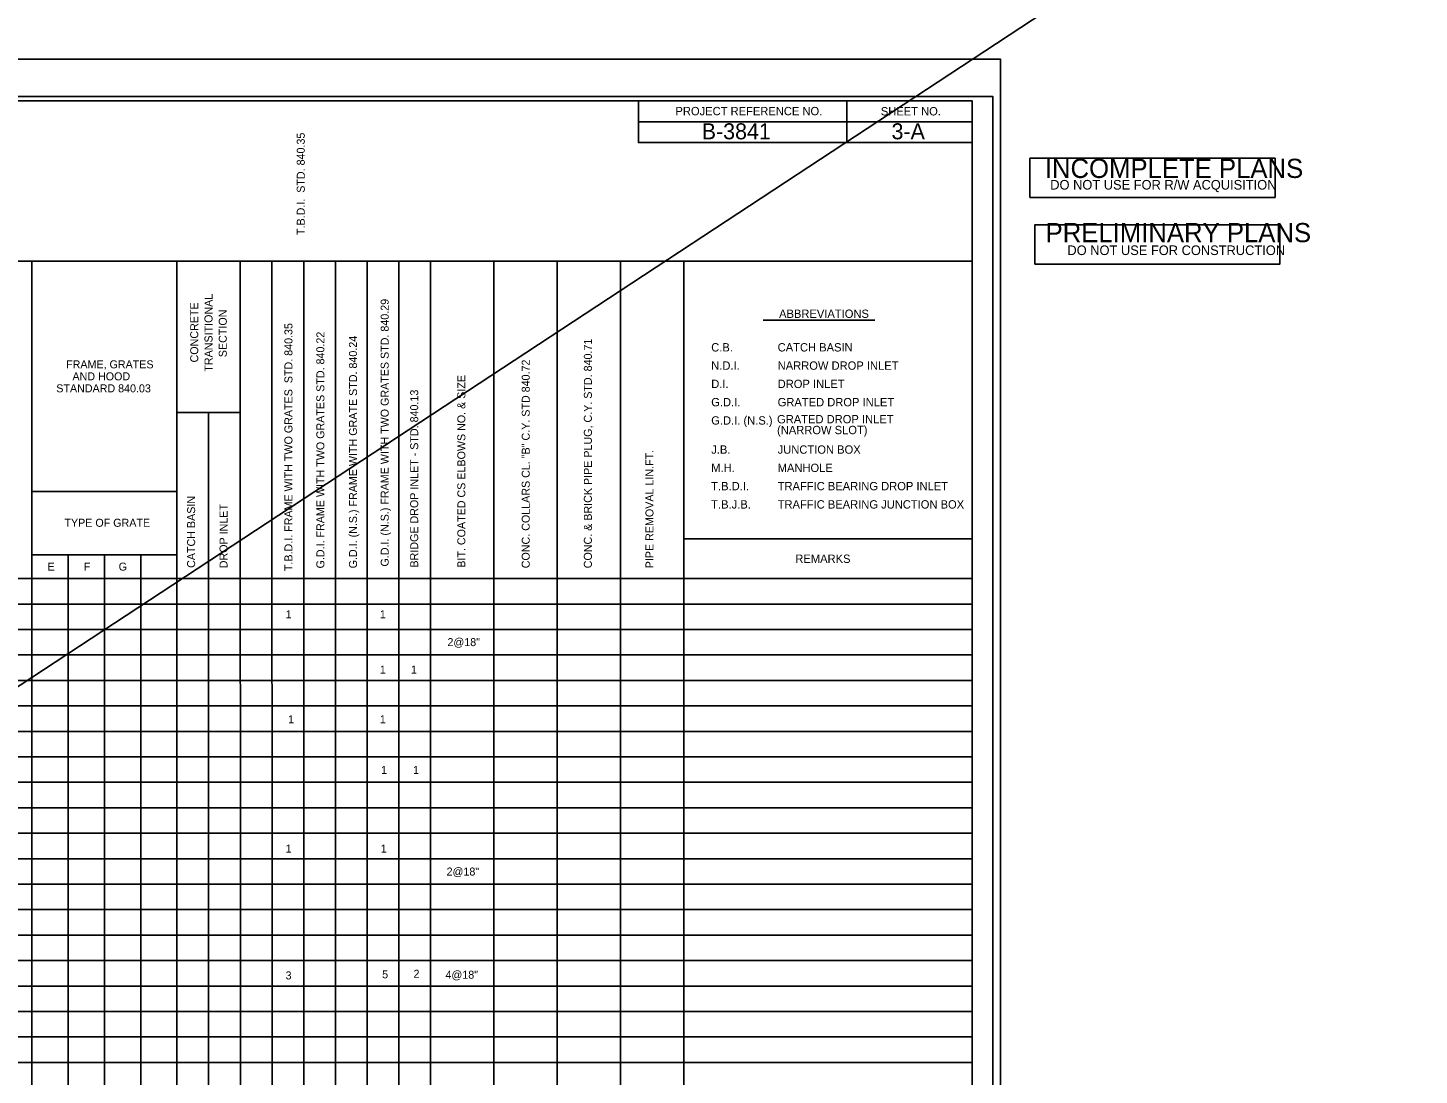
# Model space of a CAD drawing. Extents: x 573359 to 575895, y -54193 to -50493.
# Drawn here: x 574719 to 575554, y -52448 to -51820 of the extents above; entities that cross this region are included whole.
import ezdxf

# ---------------------------------------------------------------- set-up
doc = ezdxf.new("R2010")
doc.units = 0
for name, color, linetype in [('Prop Dimension Text', 7, 'Continuous'), ('Sheet Cutting Line CELL', 7, 'Continuous'), ('Sheet Pipe Summary CELL', 7, 'Continuous'), ('Sheet Pipe Summary Grid CELL', 7, 'Continuous'), ('Sheet Plot Border Inside CELL', 7, 'Continuous'), ('Sheet Plot Border Outside CELL', 7, 'Continuous'), ('Sheet Sticker Incomplete CELL', 7, 'Continuous'), ('Sheet Sticker Preliminary CELL', 7, 'Continuous')]:
    doc.layers.add(name, color=color, linetype=linetype)

msp = doc.modelspace()

# ---------------------------------------------------------------- linework, layer by layer
at = {"layer": 'Prop Dimension Text'}
msp.add_line((575553.79, -51662.96), (573359.5, -53105.6), dxfattribs=at)
at = {"layer": 'Sheet Cutting Line CELL'}
msp.add_line((575302.66, -51839.08), (573618.66, -51839.08), dxfattribs=at)
at = {"layer": 'Sheet Pipe Summary CELL'}
for p, q in [((575210.66, -51864.13), (575210.66, -51889.13)), ((575210.66, -51864.13), (575210.66, -51889.13)), ((575085.61, -51876.63), (575285.66, -51876.63)), ((575085.61, -51876.63), (575285.66, -51876.63)), ((575085.61, -51889.13), (575285.66, -51889.13)), ((575085.61, -51889.13), (575285.66, -51889.13)), ((575085.61, -51889.13), (575285.66, -51889.13)), ((575227.41, -51995.69), (575160.41, -51995.69))]:
    msp.add_line(p, q, dxfattribs=at)
for points in [[(575285.66, -51864.08), (573785.66, -51864.08), (573785.66, -52914.08), (575285.66, -52914.08)], [(575085.61, -51864.08), (575285.66, -51864.08), (575285.66, -51889.13), (575085.61, -51889.13)], [(575085.61, -51864.08), (575285.66, -51864.08), (575285.66, -51889.13), (575085.61, -51889.13)]]:
    msp.add_lwpolyline(points, close=True, dxfattribs=at)
at = {"layer": 'Sheet Pipe Summary Grid CELL'}
for p, q in [((575285.66, -51960.18), (573785.66, -51960.28)), ((574721.98, -52914.02), (574721.93, -51960.22)), ((574808.93, -52914.02), (574808.88, -51960.22)), ((574846.93, -52914.16), (574846.88, -51960.21)), ((574865.93, -52914.16), (574865.88, -51960.21)), ((574884.93, -52914.16), (574884.88, -51960.21)), ((574903.93, -52914.16), (574903.88, -51960.21)), ((574922.93, -52914.16), (574922.88, -51960.21)), ((574941.93, -52914.16), (574941.88, -51960.21)), ((574960.93, -52914.16), (574960.88, -51960.21)), ((574998.93, -52914.16), (574998.88, -51960.21)), ((574998.93, -52914.16), (574998.88, -51960.21)), ((575036.93, -52914.15), (575036.88, -51960.2)), ((575036.93, -52914.15), (575036.88, -51960.2)), ((575074.93, -52914.15), (575074.88, -51960.2)), ((575074.93, -52914.15), (575074.88, -51960.2)), ((575112.93, -52914.15), (575112.88, -51960.2)), ((575112.93, -52914.15), (575112.88, -51960.2)), ((574846.88, -52050.92), (574808.88, -52050.92)), ((574827.93, -52914.16), (574827.88, -52050.92)), ((574808.88, -52098.47), (574721.93, -52098.47)), ((575285.66, -52126.74), (575112.89, -52126.74)), ((574808.88, -52136.27), (574721.93, -52136.27)), ((574743.73, -52914.02), (574743.63, -52136.27)), ((574765.43, -52914.02), (574765.38, -52136.27)), ((574787.18, -52914.02), (574787.18, -52136.27)), ((575285.66, -52150.58), (573785.66, -52150.58)), ((575285.66, -52165.88), (573785.66, -52165.88)), ((575285.66, -52181.13), (573785.66, -52181.13)), ((575285.66, -52196.38), (573785.66, -52196.38)), ((575285.66, -52211.68), (573785.66, -52211.68)), ((575285.66, -52226.93), (573785.66, -52226.93)), ((575285.66, -52242.23), (573785.66, -52242.23)), ((575285.66, -52257.48), (573785.66, -52257.48)), ((575285.66, -52272.73), (573785.66, -52272.73)), ((575285.66, -52288.03), (573785.66, -52288.03)), ((575285.66, -52303.28), (573785.66, -52303.28)), ((575285.66, -52318.58), (573785.66, -52318.58)), ((575285.66, -52333.83), (573785.66, -52333.83)), ((575285.66, -52349.08), (573785.66, -52349.08)), ((575285.66, -52364.38), (573785.66, -52364.38)), ((575285.66, -52379.63), (573785.66, -52379.63)), ((575285.66, -52394.93), (573785.66, -52394.93)), ((575285.66, -52410.18), (573785.66, -52410.18)), ((575285.66, -52425.43), (573785.66, -52425.43)), ((575285.66, -52440.73), (573785.66, -52440.73))]:
    msp.add_line(p, q, dxfattribs=at)
at = {"layer": 'Sheet Plot Border Inside CELL'}
msp.add_lwpolyline([(573631.66, -52916.63), (575298.16, -52916.63), (575298.16, -51861.53), (573631.66, -51861.53)], close=True, dxfattribs=at)
at = {"layer": 'Sheet Plot Border Outside CELL'}
msp.add_lwpolyline([(573618.66, -52939.08), (575302.66, -52939.08), (575302.66, -51839.08), (573618.66, -51839.08)], close=True, dxfattribs=at)
at = {"layer": 'Sheet Sticker Incomplete CELL'}
msp.add_lwpolyline([(575320.36, -51922.08), (575320.36, -51898.58), (575467.36, -51898.58), (575467.36, -51922.08)], close=True, dxfattribs=at)
at = {"layer": 'Sheet Sticker Preliminary CELL'}
msp.add_lwpolyline([(575323.26, -51962.05), (575323.26, -51938.55), (575470.26, -51938.55), (575470.26, -51962.05)], close=True, dxfattribs=at)

# ---------------------------------------------------------------- texts
at = {"layer": 'Prop Dimension Text'}
for s, height, p in [('B-3841', 9.6, (575123.59, -51887.2)), ('3-A', 9.6, (575237.4, -51887.2)), ('1', 4.8, (574874.08, -52174.43)), ('1', 4.8, (574930.55, -52174.43)), ('2@18"', 4.8, (574971.09, -52191.08)), ('1', 4.8, (574930.55, -52207.59)), ('1', 4.8, (574949.16, -52207.59)), ('1', 4.8, (574875.53, -52237.34)), ('1', 4.8, (574930.55, -52237.34)), ('1', 4.8, (574931.29, -52267.74)), ('1', 4.8, (574950.47, -52267.74)), ('1', 4.8, (574874.08, -52314.87)), ('1', 4.8, (574931.1, -52314.87)), ('2@18"', 4.8, (574970.59, -52328.65)), ('3', 4.8, (574874.03, -52390.93)), ('5', 4.8, (574931.94, -52390.27)), ('2', 4.8, (574950.75, -52389.95)), ('4@18"', 4.8, (574969.92, -52390.53))]:
    msp.add_text(s, height=height, dxfattribs=at).set_placement(p)
at = {"layer": 'Sheet Pipe Summary CELL'}
for s, height, p in [('PROJECT REFERENCE NO.', 5.0001, (575107.81, -51872.78)), ('PROJECT REFERENCE NO.', 5.0001, (575107.81, -51872.78)), ('SHEET NO.', 5, (575230.96, -51872.88)), ('SHEET NO.', 5, (575230.96, -51872.88)), ('ABBREVIATIONS', 5.0001, (575169.96, -51994.29)), ('C.B.', 5, (575129.27, -52014.42)), ('CATCH BASIN', 5.0001, (575169.11, -52014.42)), ('FRAME, GRATES', 4.8, (574742.43, -52024.52)), ('AND HOOD', 4.8, (574746.23, -52031.72)), ('N.D.I.', 5, (575129.27, -52025.38)), ('NARROW DROP INLET', 5.0001, (575169.11, -52025.38)), ('STANDARD 840.03', 4.8, (574736.53, -52038.92)), ('D.I.', 5, (575129.27, -52036.35)), ('DROP INLET', 5, (575169.11, -52036.35)), ('G.D.I.', 5, (575129.27, -52047.31)), ('GRATED DROP INLET', 5.0001, (575169.11, -52047.31)), ('G.D.I. (N.S.)', 5.0001, (575129.27, -52058.27)), ('J.B.', 5, (575129.27, -52075.73)), ('JUNCTION BOX', 5.0001, (575169.11, -52075.73)), ('M.H.', 5, (575129.27, -52086.69)), ('MANHOLE', 5, (575169.11, -52086.69)), ('T.B.D.I.', 5, (575129.27, -52097.65)), ('TRAFFIC BEARING DROP INLET', 5.0001, (575169.11, -52097.65)), ('T.B.J.B.', 5, (575129.27, -52108.61)), ('TRAFFIC BEARING JUNCTION BOX', 5.0001, (575169.11, -52108.61)), ('TYPE OF GRATE', 4.8, (574741.43, -52119.52)), ('REMARKS', 5, (575179.71, -52141.19)), ('E', 4.8, (574731.28, -52145.82)), ('F', 4.8, (574753.03, -52145.82)), ('G', 4.8, (574773.93, -52145.82))]:
    msp.add_text(s, height=height, dxfattribs=at).set_placement(p)
for s, height, rotation, p in [('T.B.D.I.  STD. 840.35', 4.8, 90, (574885.53, -51944.57)), ('CONCRETE', 4.8, 90, (574821.66, -52020.99)), ('TRANSITIONAL', 4.8, 90, (574830.21, -52026.53)), ('G.D.I. (N.S.) FRAME WITH TWO GRATES STD. 840.29', 4.8, 90, (574935.87, -52143.35)), ('SECTION', 4.8, 90, (574838.76, -52017.82)), ('T.B.D.I. FRAME WITH TWO GRATES  STD. 840.35', 4.8, 90, (574878.14, -52146.11)), ('G.D.I. FRAME WITH TWO GRATES STD. 840.22', 4.8, 90, (574897.29, -52144.51)), ('G.D.I. (N.S.) FRAME WITH GRATE STD. 840.24', 4.8, 90, (574916.86, -52144.46)), ('CONC. & BRICK PIPE PLUG, C.Y. STD. 840.71', 4.8, 90, (575057.7, -52144.41)), ('CONC. COLLARS CL. "B" C.Y. STD 840.72', 4.8, 90, (575020.43, -52144.41)), ('BIT. COATED CS ELBOWS NO. & SIZE', 4.8, 90, (574981.82, -52144.07)), ('BRIDGE DROP INLET - STD. 840.13', 4.8, 90, (574953.56, -52143.96)), ('GRATED DROP INLET', 5.0001, 0.02739, (575168.74, -52057.52)), ('(NARROW SLOT)', 5.0001, 0.02739, (575168.74, -52064.02)), ('PIPE REMOVAL LIN.FT.', 4.8, 90, (575094.64, -52144.41)), ('CATCH BASIN', 4.8, 90, (574819.79, -52144.18)), ('DROP INLET', 4.8, 90, (574839.23, -52144.41))]:
    msp.add_text(s, height=height, rotation=rotation, dxfattribs=at).set_placement(p)
at = {"layer": 'Sheet Sticker Incomplete CELL'}
for s, height, p in [('INCOMPLETE PLANS', 11.52, (575329.31, -51910.38)), ('DO NOT USE FOR R/W ACQUISITION', 5.76, (575332.56, -51917.33))]:
    msp.add_text(s, height=height, dxfattribs=at).set_placement(p)
at = {"layer": 'Sheet Sticker Preliminary CELL'}
for s, height, p in [('PRELIMINARY PLANS', 11.52, (575329.76, -51948.9)), ('DO NOT USE FOR CONSTRUCTION', 5.76, (575342.86, -51956.6))]:
    msp.add_text(s, height=height, dxfattribs=at).set_placement(p)

doc.saveas('drawing.dxf')
